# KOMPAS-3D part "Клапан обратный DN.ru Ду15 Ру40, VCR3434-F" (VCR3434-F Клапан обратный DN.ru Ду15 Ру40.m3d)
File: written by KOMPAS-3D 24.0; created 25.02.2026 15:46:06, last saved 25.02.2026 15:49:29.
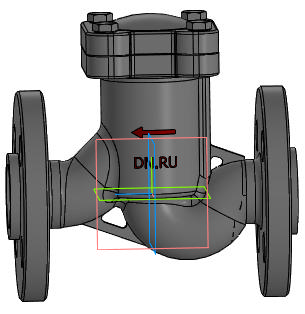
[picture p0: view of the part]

Document properties: Автор: R2D2; Полное имя файла: VCR3434-F Клапан обратный DN.ru Ду15 Ру40.cdw

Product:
- Part/product: Клапан обратный DN.ru Ду15 Ру40  | designation VCR3434-F
    Масса: 3
    Раздел спецификации: Прочие изделия
    Форматы листов документа: A3
    Примечание: D100-04050
    additional columns: D100-04050

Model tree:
1. Операция без истории:2

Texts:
  VCR3434-F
